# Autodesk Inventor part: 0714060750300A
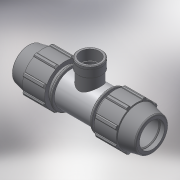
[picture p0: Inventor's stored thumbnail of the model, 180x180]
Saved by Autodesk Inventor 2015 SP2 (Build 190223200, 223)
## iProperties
Created: 2017-02
Part Number: 0714060750300A
Material: Generic
Description: PLASSON TEE WITH THREADED FEMALE OFFTAKE 75-3"-75
Document SubType Name: Modeling
Designer: KIM
Mass: 92.6774 g
Surface Area: 199.44 cm^2
Volume: 66.1981 cm^3
Density: 1 g/cm^3
Appearance: Default
Author: KIM
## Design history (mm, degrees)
derived "87140.ipt"
feature "Solid1::87140.ipt"
feature "Solid2::87140.ipt"
tag "TaggingFeature1"
body "Solid1"
other parameters: "d2" = 75, "d4" = 14.95833, "d5" = 43.08, "d7" = 134, "d11" = 5.98333, "d13" = 120 deg, "d14" = 97.5, "d15" = 12 deg, "d16" = 116.58, "d18" = 3.75, "d19" = 35 deg, "d20" = 17.5 deg, "d21" = 124.62, "d23" = 0, "d25" = 360 deg, "d27" = 2.68, "d33" = 1.5, "d42" = 64.62, "d43" = 4.02, "d46" = 2.25, "d68" = 10.77, "d76" = 84.926, "d80" = 2.54778, "d91" = 100.5, "d93" = 132, "d95" = 67.5, "d112" = 36, "d115" = 106.1575, "d116" = 135 deg, "d117" = 97.6649, "d118" = 359, "d119" = 67.5, "d121" = 0, "d122" = 67.5, "d124" = 0, "d128" = 0, "d129" = 7.5, "d130" = 10.8, "d131" = 0.3, "d132" = 0.3, "d133" = 106.1575, "d_" = 75, "E_" = 134, "l_" = 132, "l_2" = 36, "Rp_" = 84.926, "H_" = 359
